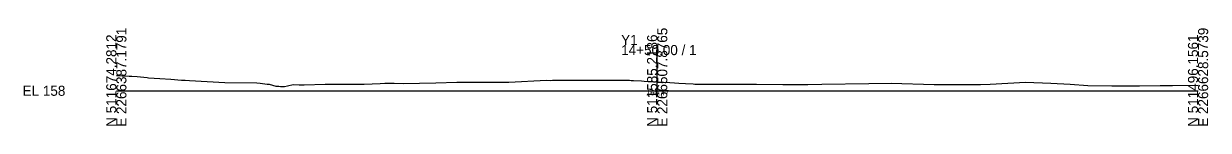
# Model space of a CAD drawing. Extents: x -516 to 303, y -10 to 5017.
# Drawn here: x -25.7 to 302.8, y 4490.3 to 4517.3 of the extents above; entities that cross this region are included whole.
import ezdxf

# ---------------------------------------------------------------- set-up
doc = ezdxf.new("R2010")
doc.units = 0
for name, color, linetype in [('Default', 7, 'Continuous'), ('Exist Cross Section Cell', 7, 'Continuous'), ('Exist XS Center Line Elevation Label', 7, 'Continuous'), ('Exist XS Ground Line', 7, 'Continuous')]:
    doc.layers.add(name, color=color, linetype=linetype)

msp = doc.modelspace()

# ---------------------------------------------------------------- linework, layer by layer
at = {"layer": 'Exist Cross Section Cell'}
for p, q in [((150, 4500), (150, 4512.69)), ((0, 4500), (150, 4500)), ((150, 4500), (300, 4500))]:
    msp.add_line(p, q, dxfattribs=at)
at = {"layer": 'Exist XS Ground Line'}
msp.add_lwpolyline([(0, 4504.23), (0.47, 4504.23), (0.97, 4504.22), (1.64, 4504.17), (2.04, 4504.14), (3.57, 4504.03), (4.27, 4504.03), (5.76, 4503.94), (8.54, 4503.64), (8.94, 4503.59), (12.05, 4503.41), (15.07, 4503.24), (18.09, 4502.96), (19.12, 4502.9), (20.28, 4502.84), (30.09, 4502.26), (38.99, 4502.2), (39.9, 4502.09), (41.2, 4501.9), (41.83, 4501.84), (42.34, 4501.8), (44.22, 4501.29), (45.09, 4501.29), (45.56, 4501.21), (46.61, 4501.21), (47.46, 4501.39), (49.04, 4501.7), (50.71, 4501.67), (52.09, 4501.64), (57.89, 4501.82), (65.75, 4501.8), (68.7, 4501.82), (73.17, 4501.99), (74.47, 4502.14), (77.06, 4502.14), (79.56, 4502.01), (88.57, 4502.18), (94.41, 4502.39), (102.97, 4502.37), (108.82, 4502.43), (119.34, 4502.9), (120.47, 4502.89), (120.99, 4502.9), (121.39, 4502.91), (122.35, 4502.92), (123.15, 4502.93), (123.74, 4502.93), (124.94, 4502.95), (126.84, 4502.97), (127.62, 4502.97), (129.94, 4502.98), (130.75, 4502.98), (133.04, 4502.97), (134.92, 4502.98), (136.14, 4502.97), (137.42, 4502.97), (139.27, 4502.97), (140.91, 4502.94), (142.35, 4502.9), (142.78, 4502.88), (143.41, 4502.84), (145.6, 4502.72), (146.38, 4502.68), (147.52, 4502.61), (147.93, 4502.59), (148.6, 4502.55), (150, 4502.47), (151.34, 4502.39), (151.78, 4502.37), (153.51, 4502.26), (154.79, 4502.19), (155.99, 4502.12), (157.88, 4502), (159.93, 4501.88), (160.45, 4501.85), (160.85, 4501.82), (168.35, 4501.82), (174.25, 4501.82), (176.45, 4501.8), (177.55, 4501.8), (184.84, 4501.76), (189.98, 4501.72), (191.8, 4501.71), (195.64, 4501.81), (208.65, 4502.02), (214.84, 4502.11), (226.79, 4501.74), (227.26, 4501.75), (232.26, 4501.74), (239.69, 4501.77), (242.34, 4501.87), (252.12, 4502.37), (259.18, 4502.15), (264.55, 4501.82), (269.45, 4501.45), (276.04, 4501.38), (276.63, 4501.36), (277.07, 4501.36), (283.79, 4501.4), (289.5, 4501.48), (292.88, 4501.45), (300, 4501.51)], dxfattribs=at)

# ---------------------------------------------------------------- texts
at = {"layer": 'Default'}
msp.add_text('-', height=0.0001, dxfattribs=at).set_placement((0, 4500))
at = {"layer": 'Exist Cross Section Cell'}
for s, p in [('E 2266507.8765', (152.8, 4490)), ('N 511674.2812', (0, 4490)), ('E 2266387.1791', (2.8, 4490)), ('N 511585.2186', (150, 4490)), ('N 511496.1561', (300, 4490)), ('E 2266628.5739', (302.8, 4490))]:
    msp.add_text(s, height=2.8, rotation=90, dxfattribs=at).set_placement(p)
for s, p in [('Y1', (140, 4512.69)), ('14+50.00 / 1', (140, 4509.89)), ('EL 158', (-26, 4498.6))]:
    msp.add_text(s, height=2.8, dxfattribs=at).set_placement(p)
at = {"layer": 'Exist XS Center Line Elevation Label'}
msp.add_text('160.47', height=1.5, dxfattribs=at).set_placement((146.95, 4498.72))

doc.saveas('drawing.dxf')
